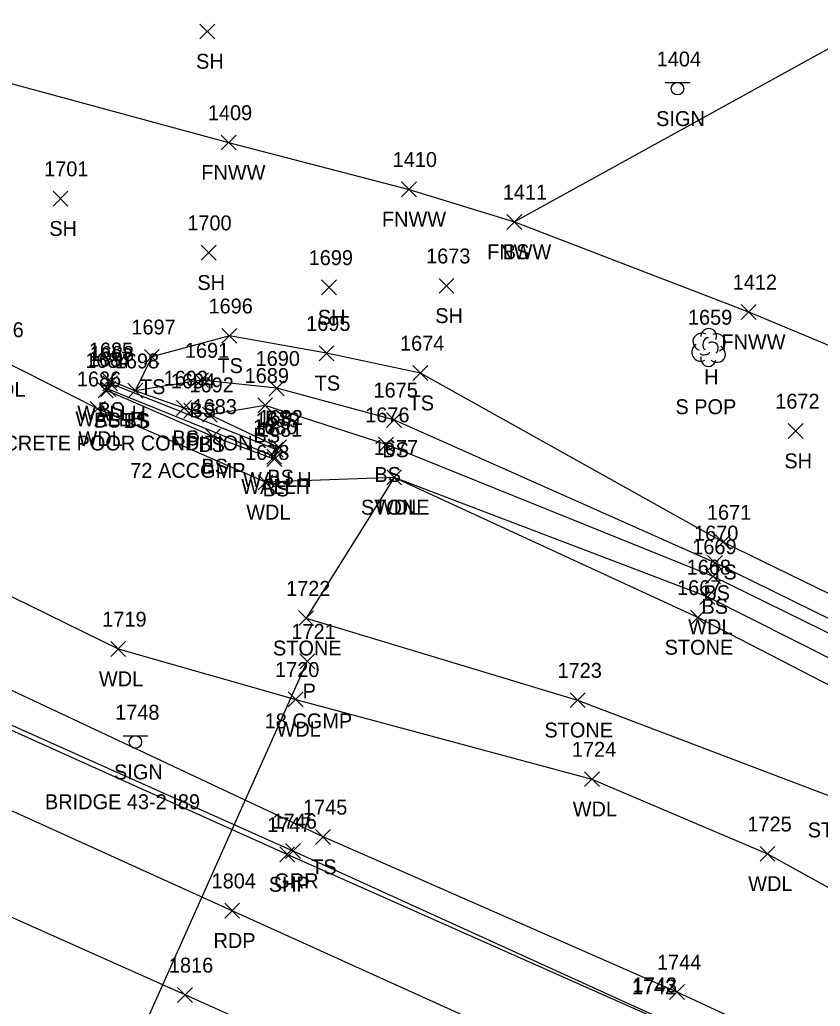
# Model space of a CAD drawing. Extents: x 1599569 to 1610055, y 642560 to 647860.
# Drawn here: x 1601916 to 1602023.4, y 647164.5 to 647296.9 of the extents above; entities that cross this region are included whole.
import ezdxf

# ---------------------------------------------------------------- set-up
doc = ezdxf.new("R2010")
doc.units = 0
for name, color, linetype in [('D_A', 7, 'Continuous'), ('D_C', 7, 'Continuous'), ('D_I', 7, 'Continuous'), ('D_TIC', 7, 'Continuous'), ('DCP', 7, 'Continuous'), ('DHW', 7, 'Continuous'), ('L_A', 7, 'Continuous'), ('L_C', 7, 'Continuous'), ('L_I', 7, 'Continuous'), ('L_TIC', 7, 'Continuous'), ('LASF', 7, 'Continuous'), ('LAWA', 7, 'Continuous'), ('LELB', 7, 'Continuous'), ('LFNC', 7, 'Continuous'), ('LTD', 7, 'Continuous'), ('P_A', 7, 'Continuous'), ('P_I', 7, 'Continuous'), ('P_TIC', 7, 'Continuous'), ('PET', 7, 'Continuous'), ('PRC', 7, 'Continuous'), ('PSP', 7, 'Continuous'), ('R_A', 7, 'Continuous'), ('R_I', 7, 'Continuous'), ('R_TIC', 7, 'Continuous'), ('RGR', 7, 'Continuous'), ('S_A', 7, 'Continuous'), ('S_C', 7, 'Continuous'), ('S_I', 7, 'Continuous'), ('SSGN', 7, 'Continuous')]:
    doc.layers.add(name, color=color, linetype=linetype)

msp = doc.modelspace()

# ---------------------------------------------------------------- linework, layer by layer
at = {"layer": 'D_TIC'}
for points in [[(1601926.87, 647246.34), (1601928.87, 647248.34)], [(1601928.87, 647246.34), (1601926.87, 647248.34)], [(1601927.12, 647247.1), (1601929.12, 647249.1)], [(1601929.12, 647247.1), (1601927.12, 647249.1)], [(1601927.12, 647247.1), (1601929.12, 647249.1)], [(1601929.12, 647247.1), (1601927.12, 647249.1)], [(1601938.01, 647243.43), (1601940.01, 647245.43)], [(1601940.01, 647243.43), (1601938.01, 647245.43)], [(1601949.36, 647238.21), (1601951.36, 647240.21)], [(1601951.36, 647238.21), (1601949.36, 647240.21)], [(1601949.36, 647238.21), (1601951.36, 647240.21)], [(1601951.36, 647238.21), (1601949.36, 647240.21)], [(1601949.13, 647237.28), (1601951.13, 647239.28)], [(1601951.13, 647237.28), (1601949.13, 647239.28)], [(1601953.57, 647209.83), (1601955.57, 647211.83)], [(1601955.57, 647209.83), (1601953.57, 647211.83)]]:
    msp.add_lwpolyline(points, dxfattribs=at)
at = {"layer": 'DCP'}
msp.add_lwpolyline([(1601954.57, 647210.83), (1601918.79, 647130.77)], dxfattribs=at)
at = {"layer": 'DHW'}
for points in [[(1601950.36, 647239.21), (1601950.13, 647238.28), (1601927.87, 647247.34), (1601928.12, 647248.1)], [(1601950.36, 647239.21), (1601928.12, 647248.1)]]:
    msp.add_lwpolyline(points, dxfattribs=at)
at = {"layer": 'L_TIC'}
for points in [[(1601940.16, 647294.31), (1601942.16, 647296.31)], [(1601942.16, 647294.31), (1601940.16, 647296.31)], [(1601943.01, 647279.41), (1601945.01, 647281.41)], [(1601945.01, 647279.41), (1601943.01, 647281.41)], [(1601967.24, 647273.13), (1601969.24, 647275.13)], [(1601969.24, 647273.13), (1601967.24, 647275.13)], [(1601920.46, 647271.88), (1601922.46, 647273.88)], [(1601922.46, 647271.88), (1601920.46, 647273.88)], [(1601981.37, 647268.76), (1601983.37, 647270.76)], [(1601983.37, 647268.76), (1601981.37, 647270.76)], [(1601981.37, 647268.76), (1601983.37, 647270.76)], [(1601983.37, 647268.76), (1601981.37, 647270.76)], [(1601940.33, 647264.63), (1601942.33, 647266.63)], [(1601942.33, 647264.63), (1601940.33, 647266.63)], [(1601956.5, 647259.97), (1601958.5, 647261.97)], [(1601958.5, 647259.97), (1601956.5, 647261.97)], [(1601972.26, 647260.19), (1601974.26, 647262.19)], [(1601974.26, 647260.19), (1601972.26, 647262.19)], [(1602012.8, 647256.69), (1602014.8, 647258.69)], [(1602014.8, 647256.69), (1602012.8, 647258.69)], [(1601943.12, 647253.48), (1601945.12, 647255.48)], [(1601945.12, 647253.48), (1601943.12, 647255.48)], [(1601956.16, 647251.14), (1601958.16, 647253.14)], [(1601958.16, 647251.14), (1601956.16, 647253.14)], [(1601932.71, 647250.66), (1601934.71, 647252.66)], [(1601934.71, 647250.66), (1601932.71, 647252.66)], [(1601926.99, 647247.57), (1601928.99, 647249.57)], [(1601928.99, 647247.57), (1601926.99, 647249.57)], [(1601939.33, 647247.53), (1601941.33, 647249.53)], [(1601941.33, 647247.53), (1601939.33, 647249.53)], [(1601968.76, 647248.48), (1601970.76, 647250.48)], [(1601970.76, 647248.48), (1601968.76, 647250.48)], [(1601926.53, 647246.18), (1601928.53, 647248.18)], [(1601928.53, 647246.18), (1601926.53, 647248.18)], [(1601930.49, 647246.11), (1601932.49, 647248.11)], [(1601932.49, 647246.11), (1601930.49, 647248.11)], [(1601930.49, 647246.11), (1601932.49, 647248.11)], [(1601932.49, 647246.11), (1601930.49, 647248.11)], [(1601930.49, 647246.11), (1601932.49, 647248.11)], [(1601932.49, 647246.11), (1601930.49, 647248.11)], [(1601930.49, 647246.11), (1601932.49, 647248.11)], [(1601932.49, 647246.11), (1601930.49, 647248.11)], [(1601949.47, 647246.44), (1601951.47, 647248.44)], [(1601951.47, 647246.44), (1601949.47, 647248.44)], [(1601925.45, 647243.69), (1601927.45, 647245.69)], [(1601927.45, 647243.69), (1601925.45, 647245.69)], [(1601937.04, 647243.79), (1601939.04, 647245.79)], [(1601939.04, 647243.79), (1601937.04, 647245.79)], [(1601947.92, 647244.15), (1601949.92, 647246.15)], [(1601949.92, 647244.15), (1601947.92, 647246.15)], [(1601940.5, 647242.9), (1601942.5, 647244.9)], [(1601942.5, 647242.9), (1601940.5, 647244.9)], [(1601940.5, 647242.9), (1601942.5, 647244.9)], [(1601942.5, 647242.9), (1601940.5, 647244.9)], [(1601965.2, 647242.2), (1601967.2, 647244.2)], [(1601967.2, 647242.2), (1601965.2, 647244.2)], [(1602019.12, 647240.71), (1602021.12, 647242.71)], [(1602021.12, 647240.71), (1602019.12, 647242.71)], [(1601940.92, 647239.99), (1601942.92, 647241.99)], [(1601942.92, 647239.99), (1601940.92, 647241.99)], [(1601949.77, 647238.52), (1601951.77, 647240.52)], [(1601951.77, 647238.52), (1601949.77, 647240.52)], [(1601964.15, 647238.88), (1601966.15, 647240.88)], [(1601966.15, 647238.88), (1601964.15, 647240.88)], [(1601949.14, 647236.94), (1601951.14, 647238.94)], [(1601951.14, 647236.94), (1601949.14, 647238.94)], [(1601949.14, 647236.94), (1601951.14, 647238.94)], [(1601951.14, 647236.94), (1601949.14, 647238.94)], [(1601965.23, 647234.49), (1601967.23, 647236.49)], [(1601967.23, 647234.49), (1601965.23, 647236.49)], [(1601965.23, 647234.49), (1601967.23, 647236.49)], [(1601967.23, 647234.49), (1601965.23, 647236.49)], [(1601947.97, 647233.83), (1601949.97, 647235.83)], [(1601949.97, 647233.83), (1601947.97, 647235.83)], [(1602009.38, 647225.8), (1602011.38, 647227.8)], [(1602011.38, 647225.8), (1602009.38, 647227.8)], [(1602008.3, 647223.02), (1602010.3, 647225.02)], [(1602010.3, 647223.02), (1602008.3, 647225.02)], [(1602008.04, 647221.19), (1602010.04, 647223.19)], [(1602010.04, 647221.19), (1602008.04, 647223.19)], [(1602007.28, 647218.45), (1602009.28, 647220.45)], [(1602009.28, 647218.45), (1602007.28, 647220.45)], [(1601953.43, 647215.6), (1601955.43, 647217.6)], [(1601955.43, 647215.6), (1601953.43, 647217.6)], [(1602005.99, 647215.7), (1602007.99, 647217.7)], [(1602007.99, 647215.7), (1602005.99, 647217.7)], [(1601928.19, 647211.47), (1601930.19, 647213.47)], [(1601930.19, 647211.47), (1601928.19, 647213.47)], [(1601952.03, 647204.71), (1601954.03, 647206.71)], [(1601954.03, 647204.71), (1601952.03, 647206.71)], [(1601989.86, 647204.6), (1601991.86, 647206.6)], [(1601991.86, 647204.6), (1601989.86, 647206.6)], [(1601991.78, 647194.01), (1601993.78, 647196.01)], [(1601993.78, 647194.01), (1601991.78, 647196.01)], [(1601955.69, 647186.25), (1601957.69, 647188.25)], [(1601957.69, 647186.25), (1601955.69, 647188.25)], [(1602015.34, 647183.99), (1602017.34, 647185.99)], [(1602017.34, 647183.99), (1602015.34, 647185.99)], [(1602003.2, 647165.45), (1602005.2, 647167.45)], [(1602005.2, 647165.45), (1602003.2, 647167.45)]]:
    msp.add_lwpolyline(points, dxfattribs=at)
at = {"layer": 'LASF'}
msp.add_lwpolyline([(1602055.25, 647191.61), (1602039.17, 647200.11), (1602006.99, 647216.7), (1601966.23, 647235.49), (1601954.43, 647216.6), (1601990.86, 647205.6), (1602026.2, 647192.2), (1602051.02, 647180.37)], dxfattribs=at)
at = {"layer": 'LAWA'}
msp.add_lwpolyline([(1602180.33, 647141.44), (1602150.88, 647154.98), (1602104.39, 647172.42), (1602082.56, 647185.2), (1602043.45, 647201.75), (1602008.28, 647219.45), (1601966.23, 647235.49), (1601948.97, 647234.83), (1601926.45, 647244.69), (1601913.4, 647251.3), (1601888.48, 647252.71), (1601887.89, 647249.04), (1601886.74, 647233.29), (1601929.19, 647212.47), (1601953.03, 647205.71), (1601992.78, 647195.01), (1602016.34, 647184.99), (1602055.62, 647163.31), (1602090.65, 647150.16), (1602117.28, 647136.84), (1602146.43, 647122.56)], dxfattribs=at)
at = {"layer": 'LELB'}
for points in [[(1602495.14, 647473.06), (1602458.34, 647453.1), (1602429.54, 647443.72), (1602409.1, 647434.56), (1602336.93, 647402.97), (1602302.05, 647391.78), (1602247.55, 647384.98), (1602215.85, 647383.22), (1602171.44, 647377.68), (1602139.34, 647373.29), (1602137.15, 647371.2), (1602092.2, 647333.52), (1602059.04, 647322.21), (1602026.95, 647294.33), (1601982.37, 647269.76)], [(1602123.64, 647113.01), (1602089.26, 647126.92), (1602047.74, 647146.19), (1602004.2, 647166.45), (1601956.69, 647187.25), (1601908.21, 647210.05), (1601851.73, 647234.01), (1601822.38, 647247.53), (1601777.77, 647267.73), (1601752.99, 647278.68), (1601718.68, 647296.47)], [(1602187.23, 647147.87), (1602152.11, 647163.1), (1602114.3, 647180.14), (1602085.42, 647192.28), (1602045.9, 647209.48), (1602010.38, 647226.8), (1601969.76, 647249.48), (1601957.16, 647252.14), (1601944.12, 647254.48), (1601933.71, 647251.66), (1601931.49, 647247.11)], [(1601950.14, 647237.94), (1601941.92, 647240.99), (1601927.53, 647247.18), (1601927.99, 647248.57), (1601931.49, 647247.11)], [(1602183.99, 647145.31), (1602151.36, 647159.84), (1602109.74, 647177.25), (1602084.28, 647188.71), (1602045.93, 647206.07), (1602009.3, 647224.02), (1601966.2, 647243.2), (1601950.47, 647247.44), (1601940.33, 647248.53), (1601931.49, 647247.11)], [(1602182.42, 647142.96), (1602151.56, 647158.23), (1602106.3, 647175.81), (1602083.94, 647187.65), (1602045.25, 647204.44), (1602009.04, 647222.19), (1601965.15, 647239.88), (1601948.92, 647245.15), (1601941.5, 647243.9), (1601938.04, 647244.79), (1601931.49, 647247.11)], [(1601950.14, 647237.94), (1601950.77, 647239.52), (1601941.5, 647243.9)]]:
    msp.add_lwpolyline(points, dxfattribs=at)
at = {"layer": 'LFNC'}
msp.add_lwpolyline([(1601805.75, 647315.97), (1601814.87, 647313.37), (1601838.01, 647307.85), (1601857.39, 647303.37), (1601875.37, 647298.23), (1601909.67, 647289.73), (1601944.01, 647280.41), (1601968.24, 647274.13), (1601982.37, 647269.76), (1602013.8, 647257.69), (1602065.95, 647235.95), (1602107.23, 647215.87), (1602133.46, 647203.49), (1602174.23, 647185.03), (1602218.38, 647164.67)], dxfattribs=at)
at = {"layer": 'LTD'}
msp.add_line((1602008.41, 647252.97), (1602008.41, 647252.97), dxfattribs=at)
msp.add_line((1602008.41, 647252.97), (1602008.41, 647252.97), dxfattribs=at)
msp.add_arc((1602008.46, 647254.41), 1.05, 335.5272, 180.9563, dxfattribs=at)
for centre, major_axis, ratio, start_param, end_param in [((1602007.62, 647253.64), (1.21, -0.51), 0.895232, 1.570796, 4.712389), ((1602009.45, 647253.56), (-1.14, -0.48), 0.949671, 1.570796, 4.712389), ((1602007.33, 647252.27), (0.58, -1.04), 0.959034, 3.141593, 6.283185), ((1602008.2, 647253.43), (-0.208, -0.792), 0.645439, 3.141593, 6.283185), ((1602008.91, 647252.81), (-0.5, 0.667), 0.989748, 3.141593, 6.283185), ((1602007.95, 647252.22), (-0.625, -0.083), 0.423636, 0, 3.141593), ((1602009.41, 647252.14), (-1.09, 0.79), 0.841452, 1.570796, 4.712389), ((1602008.41, 647251.47), (0.26, 1.06), 0.942809, 1.570796, 4.712389)]:
    msp.add_ellipse(centre, major_axis=major_axis, ratio=ratio, start_param=start_param, end_param=end_param, dxfattribs=at)
at = {"layer": 'P_TIC'}
for points in [[(1601950.88, 647183.91), (1601952.88, 647185.91)], [(1601952.88, 647183.91), (1601950.88, 647185.91)], [(1601943.5, 647176.36), (1601945.5, 647178.36)], [(1601945.5, 647176.36), (1601943.5, 647178.36)], [(1601937.18, 647165.06), (1601939.18, 647167.06)], [(1601939.18, 647165.06), (1601937.18, 647167.06)]]:
    msp.add_lwpolyline(points, dxfattribs=at)
at = {"layer": 'PET'}
msp.add_lwpolyline([(1602047.79, 647130.94), (1602008.9, 647148.2), (1601944.5, 647177.36), (1601896.5, 647199.08), (1601839.98, 647224.8), (1601799.6, 647242.94), (1601761.01, 647260.23), (1601722.86, 647277.56), (1601690.61, 647292.09), (1601662.07, 647305.04), (1601633.77, 647318.29), (1601601.82, 647332.75), (1601566.11, 647348.71), (1601533.57, 647363.83), (1601469.6, 647392.2)], dxfattribs=at)
at = {"layer": 'PRC'}
msp.add_lwpolyline([(1602004.91, 647136.4), (1601979.09, 647147.72), (1601938.18, 647166.06), (1601894.66, 647185.48), (1601851.67, 647205.52), (1601807.6, 647224.86), (1601766.29, 647241.91), (1601725.38, 647262.23), (1601683.79, 647281.85), (1601638.16, 647302.69), (1601616.13, 647312.82), (1601597.54, 647321.11), (1601562.74, 647336.75), (1601520.64, 647355.15), (1601479.31, 647373.89)], dxfattribs=at)
at = {"layer": 'PSP'}
msp.add_lwpolyline([(1602119.04, 647109.91), (1602086.42, 647124.41), (1602045.38, 647142.93), (1602000.82, 647163.15), (1601951.88, 647184.91), (1601900.46, 647208.01), (1601848.64, 647231.74), (1601816.21, 647246.31), (1601775.91, 647264.22), (1601751.81, 647275.4), (1601715.81, 647291.56), (1601673.9, 647310.83), (1601638.2, 647326.96), (1601607.44, 647341.11), (1601569.57, 647358.04), (1601539.77, 647371.54), (1601489.48, 647394.4)], dxfattribs=at)
at = {"layer": 'R_TIC'}
for points in [[(1601951.66, 647184.37), (1601953.66, 647186.37)], [(1601953.66, 647184.37), (1601951.66, 647186.37)]]:
    msp.add_lwpolyline(points, dxfattribs=at)
at = {"layer": 'RGR'}
msp.add_lwpolyline([(1602119.22, 647110.24), (1602086.6, 647124.69), (1602045.91, 647143.17), (1602000.94, 647163.41), (1601952.66, 647185.37), (1601901.1, 647208.39), (1601848.7, 647232.28), (1601817.54, 647246.54), (1601776.21, 647264.77), (1601751.92, 647275.79), (1601716.14, 647291.92), (1601674.23, 647311.09), (1601638.71, 647327.76)], dxfattribs=at)
at = {"layer": 'SSGN'}
for p, q in [((1602002.61, 647288.47), (1602005.94, 647288.47)), ((1602004.26, 647287.64), (1602004.26, 647287.64)), ((1601929.86, 647200.83), (1601933.19, 647200.83)), ((1601931.51, 647200), (1601931.51, 647200))]:
    msp.add_line(p, q, dxfattribs=at)
for centre in [(1602004.26, 647287.64), (1601931.51, 647200)]:
    msp.add_circle(centre, 0.833, dxfattribs=at)

# ---------------------------------------------------------------- texts
at = {"layer": 'D_A'}
for s, p in [('WALLH', (1601923.46, 647242.34)), ('WALLH', (1601923.71, 647243.1)), ('WALLH', (1601923.71, 647243.1)), ('P', (1601938.39, 647239.43)), ('WALLH', (1601945.95, 647234.21)), ('WALLH', (1601945.95, 647234.21)), ('WALLH', (1601945.72, 647233.28)), ('P', (1601953.95, 647205.83))]:
    msp.add_text(s, height=2, dxfattribs=at).set_placement(p)
at = {"layer": 'D_C'}
for s, p in [('CONCRETE POOR CONDITION', (1601907.86, 647239.1)), ('CONCRETE POOR CONDITION', (1601907.86, 647239.1)), ('72 ACCGMP', (1601930.82, 647235.43)), ('18 CGMP', (1601948.86, 647201.83))]:
    msp.add_text(s, height=2, dxfattribs=at).set_placement(p)
at = {"layer": 'D_I'}
for s, p in [('1688', (1601925.38, 647251.1)), ('1688', (1601925.38, 647251.1)), ('1687', (1601925.13, 647250.34)), ('1694', (1601936.27, 647247.43)), ('1679', (1601947.61, 647242.21)), ('1679', (1601947.61, 647242.21)), ('1680', (1601947.3, 647241.28)), ('1721', (1601952.44, 647213.83))]:
    msp.add_text(s, height=2, dxfattribs=at).set_placement(p)
at = {"layer": 'L_A'}
for s, p in [('SH', (1601939.65, 647290.31)), ('FNWW', (1601940.35, 647275.41)), ('FNWW', (1601964.59, 647269.13)), ('SH', (1601919.95, 647267.88)), ('FNWW', (1601978.71, 647264.76)), ('BS', (1601980.81, 647264.76)), ('SH', (1601939.82, 647260.63)), ('SH', (1601955.99, 647255.97)), ('SH', (1601971.75, 647256.19)), ('FNWW', (1602010.15, 647252.69)), ('TS', (1601942.52, 647249.48)), ('TS', (1601955.57, 647247.14)), ('H', (1602007.84, 647247.97)), ('WDL', (1601910.82, 647246.3)), ('TS', (1601932.12, 647246.66)), ('BS', (1601926.43, 647243.57)), ('BS', (1601938.77, 647243.53)), ('TS', (1601968.17, 647244.48)), ('BS', (1601925.97, 647242.18)), ('TS', (1601929.89, 647242.11)), ('BS', (1601929.93, 647242.11)), ('BS', (1601929.93, 647242.11)), ('BS', (1601929.93, 647242.11)), ('BS', (1601948.91, 647242.44)), ('WDL', (1601923.86, 647239.69)), ('BS', (1601936.48, 647239.79)), ('BS', (1601947.36, 647240.15)), ('BS', (1601939.94, 647238.9)), ('BS', (1601939.94, 647238.9)), ('BS', (1601964.64, 647238.2)), ('SH', (1602018.6, 647236.71)), ('BS', (1601940.36, 647235.99)), ('BS', (1601949.21, 647234.52)), ('BS', (1601963.59, 647234.88)), ('BS', (1601948.58, 647232.94)), ('BS', (1601948.58, 647232.94)), ('STONE', (1601961.78, 647230.49)), ('WDL', (1601963.65, 647230.49)), ('WDL', (1601946.38, 647229.83)), ('TS', (1602008.79, 647221.8)), ('BS', (1602007.74, 647219.02)), ('BS', (1602007.48, 647217.19)), ('WDL', (1602005.7, 647214.45)), ('STONE', (1601949.97, 647211.6)), ('STONE', (1602002.53, 647211.7)), ('WDL', (1601926.61, 647207.47)), ('WDL', (1601950.44, 647200.71)), ('STONE', (1601986.4, 647200.6)), ('WDL', (1601990.2, 647190.01)), ('STONE', (1602021.74, 647187.2)), ('TS', (1601955.1, 647182.25)), ('WDL', (1602013.75, 647179.99))]:
    msp.add_text(s, height=2, dxfattribs=at).set_placement(p)
at = {"layer": 'L_C'}
msp.add_text('S POP', height=2, dxfattribs=at).set_placement((1602003.98, 647243.97))
at = {"layer": 'L_I'}
for s, p in [('1409', (1601941.23, 647283.41)), ('1410', (1601966.03, 647277.13)), ('1701', (1601919.26, 647275.88)), ('1411', (1601980.81, 647272.76)), ('1411', (1601980.81, 647272.76)), ('1700', (1601938.47, 647268.63)), ('1699', (1601954.76, 647263.97)), ('1673', (1601970.52, 647264.19)), ('1412', (1602011.67, 647260.69)), ('1696', (1601941.32, 647257.48)), ('1695', (1601954.42, 647255.14)), ('1659', (1602005.66, 647255.97)), ('1706', (1601910.57, 647254.3)), ('1697', (1601930.97, 647254.66)), ('1674', (1601967.02, 647252.48)), ('1685', (1601925.25, 647251.57)), ('1691', (1601938.15, 647251.53)), ('1684', (1601924.79, 647250.18)), ('1698', (1601928.74, 647250.11)), ('1698', (1601928.74, 647250.11)), ('1698', (1601928.74, 647250.11)), ('1698', (1601928.74, 647250.11)), ('1690', (1601947.64, 647250.44)), ('1686', (1601923.65, 647247.69)), ('1693', (1601935.3, 647247.79)), ('1689', (1601946.17, 647248.15)), ('1692', (1601938.76, 647246.9)), ('1692', (1601938.76, 647246.9)), ('1675', (1601963.46, 647246.2)), ('1672', (1602017.38, 647244.71)), ('1683', (1601939.18, 647243.99)), ('1682', (1601948.03, 647242.52)), ('1676', (1601962.35, 647242.88)), ('1681', (1601947.96, 647240.94)), ('1681', (1601947.96, 647240.94)), ('1677', (1601963.49, 647238.49)), ('1677', (1601963.49, 647238.49)), ('1678', (1601946.23, 647237.83)), ('1671', (1602008.21, 647229.8)), ('1670', (1602006.48, 647227.02)), ('1669', (1602006.24, 647225.19)), ('1668', (1602005.49, 647222.45)), ('1722', (1601951.73, 647219.6)), ('1667', (1602004.2, 647219.7)), ('1719', (1601927.06, 647215.47)), ('1720', (1601950.25, 647208.71)), ('1723', (1601988.16, 647208.6)), ('1724', (1601990.09, 647198.01)), ('1745', (1601954, 647190.25)), ('1725', (1602013.64, 647187.99)), ('1744', (1602001.51, 647169.45))]:
    msp.add_text(s, height=2, dxfattribs=at).set_placement(p)
at = {"layer": 'P_A'}
for s, p in [('SHP', (1601949.41, 647179.91)), ('RDP', (1601941.99, 647172.36))]:
    msp.add_text(s, height=2, dxfattribs=at).set_placement(p)
at = {"layer": 'P_I'}
for s, p in [('1747', (1601949.19, 647187.91)), ('1804', (1601941.73, 647180.36)), ('1816', (1601936, 647169.06)), ('1742', (1601998.13, 647166.15))]:
    msp.add_text(s, height=2, dxfattribs=at).set_placement(p)
at = {"layer": 'R_A'}
msp.add_text('GRR', height=2, dxfattribs=at).set_placement((1601950.15, 647180.37))
at = {"layer": 'R_I'}
for s, p in [('1746', (1601949.91, 647188.37)), ('1743', (1601998.25, 647166.41))]:
    msp.add_text(s, height=2, dxfattribs=at).set_placement(p)
at = {"layer": 'S_A'}
for p in [(1602001.39, 647282.62), (1601928.64, 647194.98)]:
    msp.add_text('SIGN', height=2, dxfattribs=at).set_placement(p)
at = {"layer": 'S_C'}
msp.add_text('BRIDGE 43-2 I89', height=2, dxfattribs=at).set_placement((1601919.37, 647190.98))
at = {"layer": 'S_I'}
for s, p in [('1404', (1602001.47, 647290.62)), ('1748', (1601928.79, 647202.98))]:
    msp.add_text(s, height=2, dxfattribs=at).set_placement(p)

doc.saveas('drawing.dxf')
